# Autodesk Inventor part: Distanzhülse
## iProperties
Created: 2003-04
Part Number: Distanzhülse
Material: Messing
Document SubType Name: Modellieren
Designer: Administrator
Control State: 0
Master: False
Checked Out: False
Shininess: 20.0
Angle Display Precision: 2
Document Length Units: 11269
Document Angle Units: 11279
Document Time Units: 11290
Document Mass Units: 11283
Document Length Units Precision: 3
Document Angle Units Precision: 2
Density: 0.0
Volumn: 0.0
Area: 0.0
PropertySet Name: Model Information
Author: Administrator
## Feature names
1. Drehung1 [Revolution]
2. Fase1 [Chamfer]
